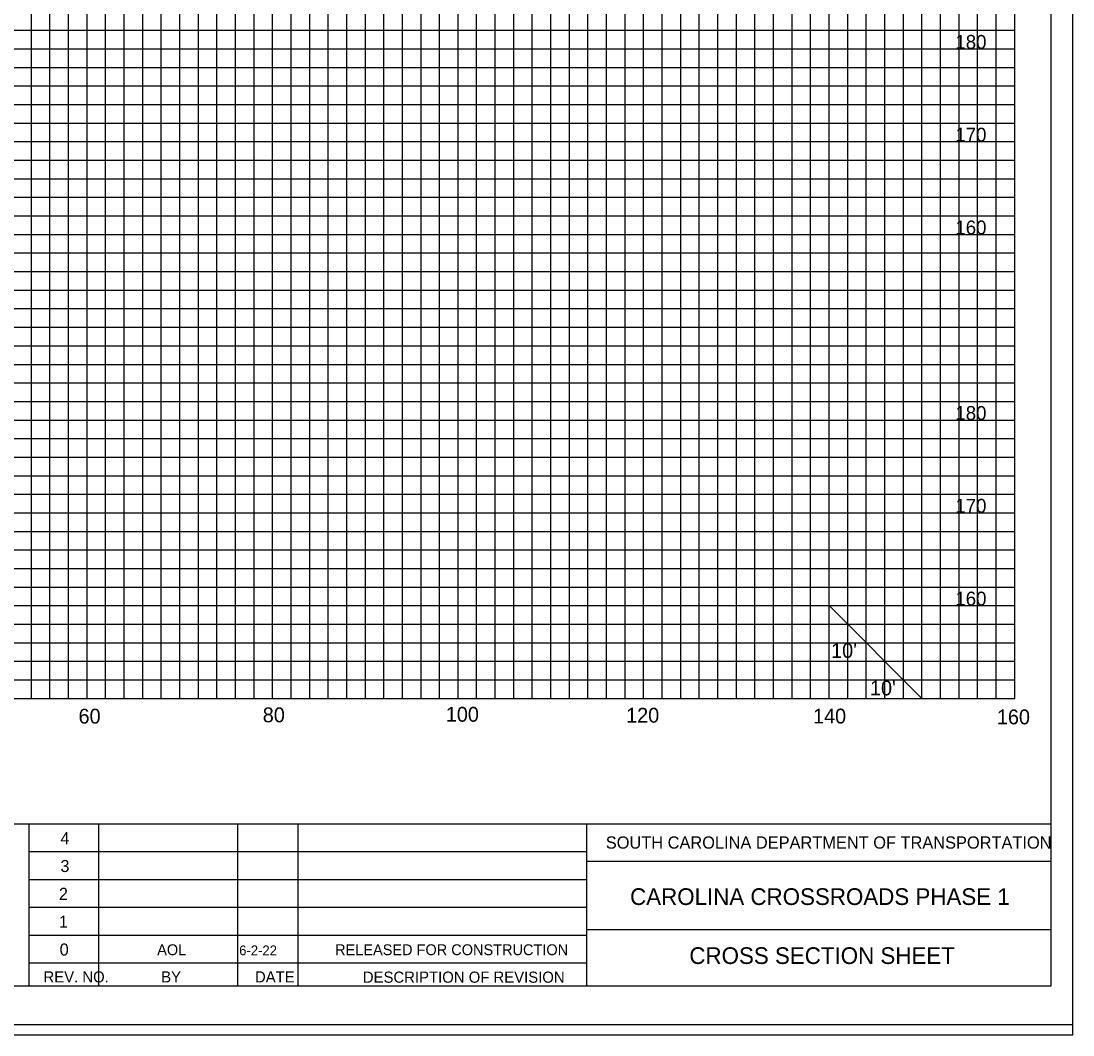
# Model space of a CAD drawing. Extents: x 967 to 1326, y 964 to 2864.
# Drawn here: x 1212.9 to 1326.3, y 1803.7 to 1913 of the extents above; entities that cross this region are included whole.
import ezdxf

# ---------------------------------------------------------------- set-up
doc = ezdxf.new("R2010")
doc.units = 0
for name, color, linetype in [('Default', 7, 'Continuous'), ('RD_EX_RW', 7, 'Continuous'), ('RD_PD_Final_TX', 7, 'Continuous'), ('RD_SHT_ShtClip', 7, 'Continuous'), ('RD_XS_TX_Elev_PR', 7, 'Continuous'), ('RD_XS_TX_ShdSlope', 7, 'Continuous'), ('RD_XS_TX_Slope', 7, 'Continuous')]:
    doc.layers.add(name, color=color, linetype=linetype)

msp = doc.modelspace()

# ---------------------------------------------------------------- linework, layer by layer
at = {"layer": 'RD_EX_RW'}
for p, q in [((1220, 1840), (1220, 2010)), ((1230, 1840), (1230, 2010)), ((1240, 1840), (1240, 2010)), ((1250, 1840), (1250, 2010)), ((1260, 1840), (1260, 2010)), ((1270, 1840), (1270, 2010)), ((1280, 1840), (1280, 2010)), ((1290, 1840), (1290, 2010)), ((1300, 1840), (1300, 2010)), ((1310, 1840), (1310, 2010)), ((1320, 1840), (1320, 2010)), ((1000, 1910), (1320, 1910)), ((1000, 1900), (1320, 1900)), ((1000, 1890), (1320, 1890)), ((1000, 1880), (1320, 1880)), ((1000, 1870), (1320, 1870)), ((1000, 1860), (1320, 1860)), ((1000, 1850), (1320, 1850)), ((1000, 1840), (1320, 1840))]:
    msp.add_line(p, q, dxfattribs=at)
at = {"layer": 'RD_PD_Final_TX'}
for p, q in [((1323.89, 2018.46), (1323.89, 1808.98)), ((996.11, 1826.49), (1323.89, 1826.49)), ((1213.76, 1808.94), (1213.76, 1826.49)), ((1221.26, 1808.95), (1221.26, 1826.48)), ((1236.26, 1808.95), (1236.26, 1826.48)), ((1242.76, 1808.95), (1242.76, 1826.48)), ((1273.88, 1808.98), (1273.88, 1826.49)), ((1213.76, 1823.48), (1273.88, 1823.48)), ((1323.93, 1822.43), (1273.88, 1822.43)), ((1213.76, 1820.48), (1273.88, 1820.48)), ((1213.76, 1817.48), (1273.88, 1817.48)), ((1213.76, 1814.48), (1273.88, 1814.48)), ((1323.89, 1815.04), (1273.88, 1815.04)), ((1213.76, 1811.48), (1273.88, 1811.48)), ((1323.89, 1808.98), (996.11, 1808.98))]:
    msp.add_line(p, q, dxfattribs=at)
at = {"layer": 'RD_SHT_ShtClip'}
for p, q in [((1214, 1840), (1214, 2010)), ((1216, 1840), (1216, 2010)), ((1218, 1840), (1218, 2010)), ((1222, 1840), (1222, 2010)), ((1224, 1840), (1224, 2010)), ((1226, 1840), (1226, 2010)), ((1228, 1840), (1228, 2010)), ((1232, 1840), (1232, 2010)), ((1234, 1840), (1234, 2010)), ((1236, 1840), (1236, 2010)), ((1238, 1840), (1238, 2010)), ((1242, 1840), (1242, 2010)), ((1244, 1840), (1244, 2010)), ((1246, 1840), (1246, 2010)), ((1248, 1840), (1248, 2010)), ((1252, 1840), (1252, 2010)), ((1254, 1840), (1254, 2010)), ((1256, 1840), (1256, 2010)), ((1258, 1840), (1258, 2010)), ((1262, 1840), (1262, 2010)), ((1264, 1840), (1264, 2010)), ((1266, 1840), (1266, 2010)), ((1268, 1840), (1268, 2010)), ((1272, 1840), (1272, 2010)), ((1274, 1840), (1274, 2010)), ((1276, 1840), (1276, 2010)), ((1278, 1840), (1278, 2010)), ((1282, 1840), (1282, 2010)), ((1284, 1840), (1284, 2010)), ((1286, 1840), (1286, 2010)), ((1288, 1840), (1288, 2010)), ((1292, 1840), (1292, 2010)), ((1294, 1840), (1294, 2010)), ((1296, 1840), (1296, 2010)), ((1298, 1840), (1298, 2010)), ((1302, 1840), (1302, 2010)), ((1304, 1840), (1304, 2010)), ((1306, 1840), (1306, 2010)), ((1308, 1840), (1308, 2010)), ((1312, 1840), (1312, 2010)), ((1314, 1840), (1314, 2010)), ((1316, 1840), (1316, 2010)), ((1318, 1840), (1318, 2010)), ((1000, 1912), (1320, 1912)), ((1000, 1908), (1320, 1908)), ((1000, 1906), (1320, 1906)), ((1000, 1904), (1320, 1904)), ((1000, 1902), (1320, 1902)), ((1000, 1898), (1320, 1898)), ((1000, 1896), (1320, 1896)), ((1000, 1894), (1320, 1894)), ((1000, 1892), (1320, 1892)), ((1000, 1888), (1320, 1888)), ((1000, 1886), (1320, 1886)), ((1000, 1884), (1320, 1884)), ((1000, 1882), (1320, 1882)), ((1000, 1878), (1320, 1878)), ((1000, 1876), (1320, 1876)), ((1000, 1874), (1320, 1874)), ((1000, 1872), (1320, 1872)), ((1000, 1868), (1320, 1868)), ((1000, 1866), (1320, 1866)), ((1000, 1864), (1320, 1864)), ((1000, 1862), (1320, 1862)), ((1000, 1858), (1320, 1858)), ((1000, 1856), (1320, 1856)), ((1000, 1854), (1320, 1854)), ((1000, 1852), (1320, 1852)), ((1000, 1848), (1320, 1848)), ((1000, 1846), (1320, 1846)), ((1000, 1844), (1320, 1844)), ((1000, 1842), (1320, 1842))]:
    msp.add_line(p, q, dxfattribs=at)
at = {"layer": 'RD_XS_TX_Elev_PR'}
for points in [[(967.41, 1803.72), (1326.28, 1803.72), (1326.28, 2023.72), (967.41, 2023.72)], [(988.52, 1804.84), (1326.28, 1804.84), (1326.28, 2022.6), (988.52, 2022.6)]]:
    msp.add_lwpolyline(points, close=True, dxfattribs=at)
at = {"layer": 'RD_XS_TX_Slope'}
msp.add_line((1300, 1850), (1310, 1840), dxfattribs=at)

# ---------------------------------------------------------------- texts
at = {"layer": 'Default'}
for s, p in [('180', (1313.61, 1910)), ('170', (1313.61, 1900)), ('160', (1313.61, 1890)), ('180', (1313.61, 1870)), ('170', (1313.61, 1860)), ('160', (1313.61, 1850))]:
    msp.add_text(s, height=1.5, dxfattribs=at).set_placement(p)
at = {"layer": 'RD_XS_TX_ShdSlope'}
for s, height, p in [('AOL', 1.17, (1227.56, 1812.32)), ('6-2-22', 1.053, (1236.4, 1812.31)), ('RELEASED FOR CONSTRUCTION', 1.17, (1246.74, 1812.32))]:
    msp.add_text(s, height=height, dxfattribs=at).set_placement(p)
at = {"layer": 'RD_XS_TX_Slope'}
for s, height, p in [("10'", 1.6, (1300.21, 1844.36)), ("10'", 1.6, (1304.4, 1840.32)), ('60', 1.6, (1219.08, 1837.28)), ('80', 1.6, (1238.94, 1837.42)), ('100', 1.6, (1258.67, 1837.48)), ('120', 1.6, (1278.11, 1837.38)), ('140', 1.6, (1298.26, 1837.29)), ('160', 1.6, (1318.08, 1837.2)), ('4', 1.3, (1217.13, 1824.28)), ('SOUTH CAROLINA DEPARTMENT OF TRANSPORTATION', 1.32, (1275.92, 1823.8)), ('3', 1.3, (1217.13, 1821.28)), ('2', 1.3, (1216.97, 1818.28)), ('1', 1.3, (1216.97, 1815.28)), ('0', 1.3, (1217.05, 1812.28)), ('REV. NO.', 1.2, (1215.3, 1809.38)), ('BY', 1.2, (1227.99, 1809.38)), ('DATE', 1.2, (1238.1, 1809.38)), ('DESCRIPTION OF REVISION', 1.2, (1249.73, 1809.35))]:
    msp.add_text(s, height=height, dxfattribs=at).set_placement(p)
for s, p in [('CAROLINA CROSSROADS PHASE 1', (1278.54, 1817.73)), ('CROSS SECTION SHEET', (1284.93, 1811.37))]:
    msp.add_text(s, height=1.8, rotation=0, dxfattribs=at).set_placement(p)

doc.saveas('drawing.dxf')
